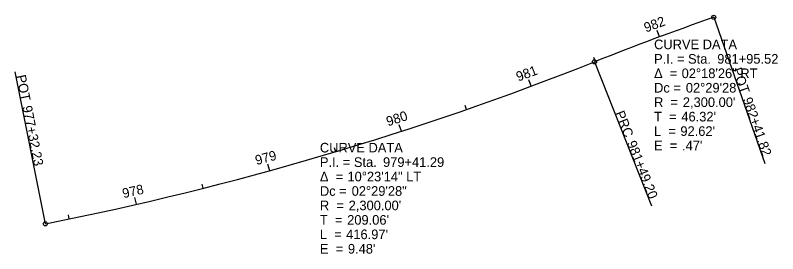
# Model space of a CAD drawing. Extents: x 2192966 to 2197975, y 660343 to 661858.
# Drawn here: x 2192966 to 2193521, y 660343 to 660517 of the extents above; entities that cross this region are included whole.
import ezdxf

# ---------------------------------------------------------------- set-up
doc = ezdxf.new("R2010")
doc.units = 0
for name, color, linetype in [('PM_X_Cells', 7, 'Continuous'), ('PM_X_CL_Double_Solid', 7, 'Continuous'), ('PM_X_Crosswalk', 7, 'Continuous'), ('PM_X_Dotted_Line', 7, 'Continuous'), ('PM_X_Edge_Line', 7, 'Continuous'), ('PM_X_Stop_Line', 7, 'Continuous'), ('PM_X_Yield_Line', 7, 'Continuous')]:
    doc.layers.add(name, color=color, linetype=linetype)

msp = doc.modelspace()

# ---------------------------------------------------------------- linework, layer by layer
at = {"layer": 'PM_X_Cells'}
for p, q in [((2193474.29, 660515.23), (2193511.48, 660409.05)), ((2193387.52, 660482.85), (2193428.96, 660378.26)), ((2192988.1, 660365.14), (2192966.2, 660475.49)), ((2193247.12, 660432.43), (2193245.59, 660437.19))]:
    msp.add_line(p, q, dxfattribs=at)
for centre in [(2193474.29, 660515.23), (2193387.52, 660482.85), (2192988.1, 660365.14)]:
    msp.add_circle(centre, 1.5, dxfattribs=at)
at = {"layer": 'PM_X_CL_Double_Solid'}
for p, q in [((2193474.29, 660515.23), (2193511.48, 660409.05)), ((2193434.95, 660501.04), (2193433.9, 660503.85)), ((2193387.52, 660482.85), (2193428.96, 660378.26)), ((2192988.1, 660365.14), (2192966.2, 660475.49)), ((2193341.59, 660465.22), (2193340.54, 660468.03)), ((2193247.12, 660432.43), (2193245.59, 660437.19)), ((2193151.32, 660403.77), (2193150.53, 660406.67)), ((2193054.37, 660379.31), (2193053.7, 660382.24))]:
    msp.add_line(p, q, dxfattribs=at)
for centre in [(2193474.29, 660515.23), (2193387.52, 660482.85), (2192988.1, 660365.14)]:
    msp.add_circle(centre, 1.5, dxfattribs=at)
at = {"layer": 'PM_X_Edge_Line'}
for centre, start, end in [((2194234.74, 658344.58), 109.30709, 111.61437), ((2192540.29, 662621.12), 281.22716, 291.61438)]:
    msp.add_arc(centre, 2300, start, end, dxfattribs=at)
at = {"layer": 'PM_X_Yield_Line'}
for p, q in [((2193474.29, 660515.23), (2193511.48, 660409.05)), ((2193434.95, 660501.04), (2193433.21, 660505.73)), ((2193388.26, 660483.15), (2193387.16, 660485.94)), ((2193387.52, 660482.85), (2193428.96, 660378.26)), ((2192988.1, 660365.14), (2192966.2, 660475.49)), ((2193341.59, 660465.22), (2193339.84, 660469.91)), ((2193294.53, 660448.31), (2193293.55, 660451.14)), ((2193247.12, 660432.43), (2193245.59, 660437.19)), ((2193199.38, 660417.58), (2193198.52, 660420.46)), ((2193151.32, 660403.77), (2193150, 660408.6)), ((2193102.98, 660391.02), (2193102.25, 660393.93)), ((2193054.37, 660379.31), (2193053.25, 660384.19)), ((2193005.52, 660368.67), (2193004.91, 660371.61))]:
    msp.add_line(p, q, dxfattribs=at)
for centre in [(2193474.29, 660515.23), (2193387.52, 660482.85), (2192988.1, 660365.14)]:
    msp.add_circle(centre, 1.5, dxfattribs=at)

# ---------------------------------------------------------------- texts
at = {"layer": 'PM_X_Cells'}
for s, rotation, p in [('POT', 289.3071, (2193487.73, 660477.22)), ('POT', 281.2272, (2192966.87, 660472.72)), ('982+41.82', 289.3071, (2193495.27, 660455.67)), ('977+32.23', 281.2272, (2192971.31, 660450.34)), ('980', 17.8976, (2193237.36, 660435.97)), ('PRC', 291.6144, (2193402.37, 660445.68)), ('981+49.20', 291.6144, (2193410.98, 660423.95))]:
    msp.add_text(s, height=7, rotation=rotation, dxfattribs=at).set_placement(p)
at = {"layer": 'PM_X_CL_Double_Solid'}
for s, rotation, p in [('POT', 289.3071, (2193487.73, 660477.22)), ('POT', 281.2272, (2192966.87, 660472.72)), ('982+41.82', 289.3071, (2193495.27, 660455.67)), ('977+32.23', 281.2272, (2192971.31, 660450.34)), ('980', 17.8976, (2193237.36, 660435.97)), ('PRC', 291.6144, (2193402.37, 660445.68)), ('981+49.20', 291.6144, (2193410.98, 660423.95))]:
    msp.add_text(s, height=7, rotation=rotation, dxfattribs=at).set_placement(p)
at = {"layer": 'PM_X_Crosswalk'}
for s, p in [('CURVE DATA', (2193430.9, 660492.04)), ('P.I. = Sta. ', (2193430.9, 660481.54)), ('981+95.52', (2193476.82, 660481.54)), ('Δ  = ', (2193430.9, 660471.04)), ('02°18\'26" RT', (2193450.96, 660471.04)), ('Dc = ', (2193430.9, 660460.54)), ('02°29\'28"', (2193454, 660460.54)), ('R  = ', (2193430.9, 660450.04)), ("2,300.00'", (2193451.82, 660450.04)), ('T  = ', (2193430.9, 660439.54)), ("46.32'", (2193450.73, 660439.54)), ('L  = ', (2193430.9, 660429.04)), ("92.62'", (2193450.02, 660429.04)), ('CURVE DATA', (2193187.81, 660417)), ('E  = ', (2193430.9, 660418.54)), (".47'", (2193451.28, 660418.54)), ('P.I. = Sta. ', (2193187.81, 660406.5)), ('979+41.29', (2193233.73, 660406.5)), ('Δ  = ', (2193187.81, 660396)), ('10°23\'14" LT', (2193207.86, 660396)), ('Dc = ', (2193187.81, 660385.5)), ('02°29\'28"', (2193210.91, 660385.5)), ('R  = ', (2193187.81, 660375)), ("2,300.00'", (2193208.73, 660375)), ('T  = ', (2193187.81, 660364.5)), ("209.06'", (2193207.64, 660364.5)), ('L  = ', (2193187.81, 660354)), ("416.97'", (2193206.92, 660354)), ('E  = ', (2193187.81, 660343.5)), ("9.48'", (2193208.19, 660343.5))]:
    msp.add_text(s, height=7, dxfattribs=at).set_placement(p)
at = {"layer": 'PM_X_Dotted_Line'}
for s, p in [('CURVE DATA', (2193430.9, 660492.04)), ('P.I. = Sta. ', (2193430.9, 660481.54)), ('981+95.52', (2193476.82, 660481.54)), ('Δ  = ', (2193430.9, 660471.04)), ('02°18\'26" RT', (2193450.96, 660471.04)), ('Dc = ', (2193430.9, 660460.54)), ('02°29\'28"', (2193454, 660460.54)), ('R  = ', (2193430.9, 660450.04)), ("2,300.00'", (2193451.82, 660450.04)), ('T  = ', (2193430.9, 660439.54)), ("46.32'", (2193450.73, 660439.54)), ('L  = ', (2193430.9, 660429.04)), ("92.62'", (2193450.02, 660429.04)), ('CURVE DATA', (2193187.81, 660417)), ('E  = ', (2193430.9, 660418.54)), (".47'", (2193451.28, 660418.54)), ('P.I. = Sta. ', (2193187.81, 660406.5)), ('979+41.29', (2193233.73, 660406.5)), ('Δ  = ', (2193187.81, 660396)), ('10°23\'14" LT', (2193207.86, 660396)), ('Dc = ', (2193187.81, 660385.5)), ('02°29\'28"', (2193210.91, 660385.5)), ('R  = ', (2193187.81, 660375)), ("2,300.00'", (2193208.73, 660375)), ('T  = ', (2193187.81, 660364.5)), ("209.06'", (2193207.64, 660364.5)), ('L  = ', (2193187.81, 660354)), ("416.97'", (2193206.92, 660354)), ('E  = ', (2193187.81, 660343.5)), ("9.48'", (2193208.19, 660343.5))]:
    msp.add_text(s, height=7, dxfattribs=at).set_placement(p)
at = {"layer": 'PM_X_Stop_Line'}
for s, p in [('CURVE DATA', (2193430.9, 660492.04)), ('P.I. = Sta. ', (2193430.9, 660481.54)), ('981+95.52', (2193476.82, 660481.54)), ('Δ  = ', (2193430.9, 660471.04)), ('02°18\'26" RT', (2193450.96, 660471.04)), ('Dc = ', (2193430.9, 660460.54)), ('02°29\'28"', (2193454, 660460.54)), ('R  = ', (2193430.9, 660450.04)), ("2,300.00'", (2193451.82, 660450.04)), ('T  = ', (2193430.9, 660439.54)), ("46.32'", (2193450.73, 660439.54)), ('L  = ', (2193430.9, 660429.04)), ("92.62'", (2193450.02, 660429.04)), ('CURVE DATA', (2193187.81, 660417)), ('E  = ', (2193430.9, 660418.54)), (".47'", (2193451.28, 660418.54)), ('P.I. = Sta. ', (2193187.81, 660406.5)), ('979+41.29', (2193233.73, 660406.5)), ('Δ  = ', (2193187.81, 660396)), ('10°23\'14" LT', (2193207.86, 660396)), ('Dc = ', (2193187.81, 660385.5)), ('02°29\'28"', (2193210.91, 660385.5)), ('R  = ', (2193187.81, 660375)), ("2,300.00'", (2193208.73, 660375)), ('T  = ', (2193187.81, 660364.5)), ("209.06'", (2193207.64, 660364.5)), ('L  = ', (2193187.81, 660354)), ("416.97'", (2193206.92, 660354)), ('E  = ', (2193187.81, 660343.5)), ("9.48'", (2193208.19, 660343.5))]:
    msp.add_text(s, height=7, dxfattribs=at).set_placement(p)
at = {"layer": 'PM_X_Yield_Line'}
for s, rotation, p in [('982', 20.3489, (2193425.06, 660504.17)), ('981', 20.3888, (2193332.08, 660468.48)), ('POT', 289.3071, (2193487.73, 660477.22)), ('POT', 281.2272, (2192966.87, 660472.72)), ('982+41.82', 289.3071, (2193495.27, 660455.67)), ('977+32.23', 281.2272, (2192971.31, 660450.34)), ('980', 17.8976, (2193237.36, 660435.97)), ('PRC', 291.6144, (2193402.37, 660445.68)), ('981+49.20', 291.6144, (2193410.98, 660423.95)), ('979', 15.4065, (2193141.79, 660407.75)), ('978', 12.9154, (2193044.96, 660383.69))]:
    msp.add_text(s, height=7, rotation=rotation, dxfattribs=at).set_placement(p)

doc.saveas('drawing.dxf')
